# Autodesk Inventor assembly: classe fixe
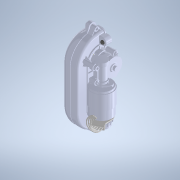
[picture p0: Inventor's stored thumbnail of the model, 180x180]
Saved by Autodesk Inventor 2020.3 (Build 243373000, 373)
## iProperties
Created: 2019-01
Part Number: classe fixe
Document SubType Name: Assembly
Designer: ficho
Mass: 916.279 g
Surface Area: 9957.84 cm^2
Volume: 858.267 cm^3
Density: 1.06759 g/cm^3
Sending System: SolidWorks 2015
Last Author: adrien
Last Saved: 2019-01-25
Author: ficho
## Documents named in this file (2)
- D:\travail\année 2020-2021\2I2D\laveur de vitre\Lave vitre\4 Dossier Ressources\1 Modèles 3D Solidworks\classe fixe.iam
- D:\travail\année 2020-2021\2I2D\laveur de vitre\Lave vitre\4 Dossier Ressources\1 Modèles 3D Solidworks\Chenilles complet.iam
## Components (1 placed, 1 different names)
1. Chenilles complet:2 [sub-assembly]
